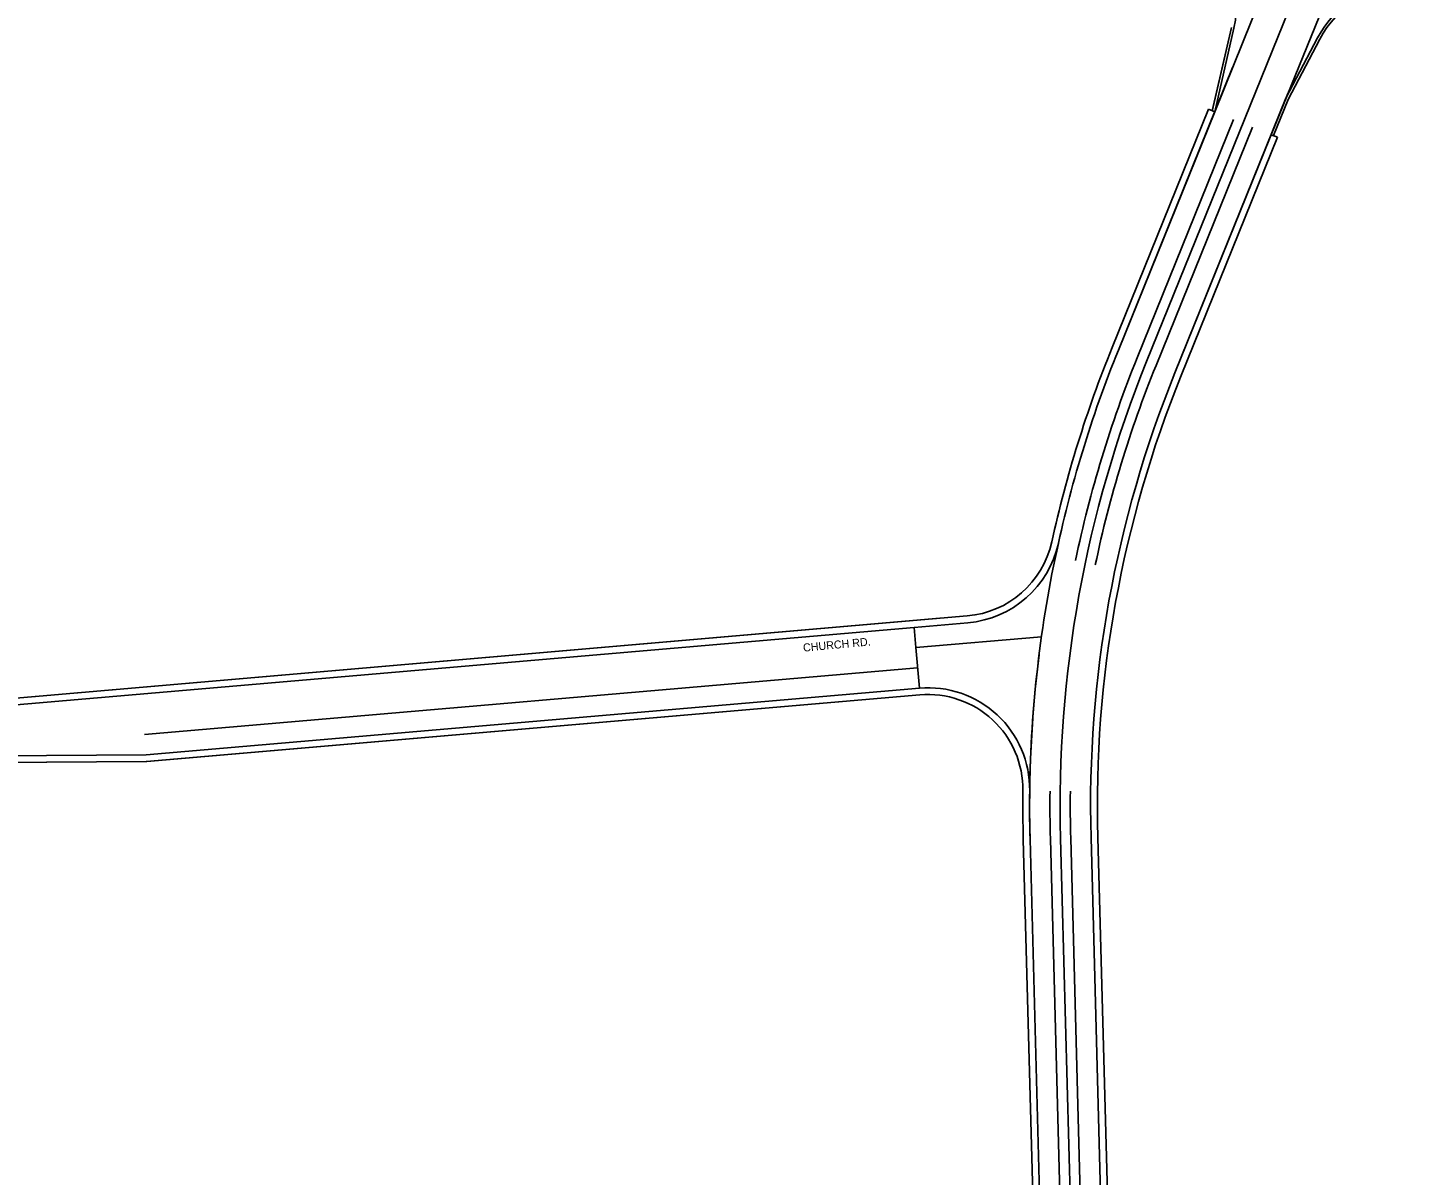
# Model space of a CAD drawing. Extents: x 2315515 to 2326910, y 758186 to 762794.
# Drawn here: x 2319969 to 2320783, y 758863 to 759540 of the extents above; entities that cross this region are included whole.
import ezdxf

# ---------------------------------------------------------------- set-up
doc = ezdxf.new("R2010")
doc.units = 0
for name, color, linetype in [('Default', 7, 'Continuous'), ('Draft_Corr_Range_Design', 7, 'Continuous'), ('E_Terrain_Exterior', 7, 'Continuous'), ('Pavement Marking Yellow', 7, 'Continuous'), ('Road_Curb_Face', 7, 'Continuous'), ('TL_End Condition Ditch In', 7, 'Continuous'), ('TL_End Condition Ditch Out', 7, 'Continuous'), ('TL_Pavement Centerline', 7, 'Continuous')]:
    doc.layers.add(name, color=color, linetype=linetype)

msp = doc.modelspace()

# ---------------------------------------------------------------- linework, layer by layer
at = {"layer": 'Default'}
for p, q in [((2320629.39, 759343.06), (2320782.39, 759721.29)), ((2320629.39, 759343.06), (2320782.39, 759721.29)), ((2320629.39, 759343.06), (2320782.39, 759721.29)), ((2320602.26, 758186.07), (2320578.57, 759061.64)), ((2320602.26, 758186.07), (2320578.57, 759061.64)), ((2320602.26, 758186.07), (2320578.57, 759061.64))]:
    msp.add_line(p, q, dxfattribs=at)
msp.add_arc((2321278.32, 759080.58), 700, 157.9768, 181.54992, dxfattribs=at)
msp.add_arc((2321278.32, 759080.58), 700, 157.9768, 181.54992, dxfattribs=at)
msp.add_arc((2321278.32, 759080.58), 700, 157.9768, 181.54992, dxfattribs=at)
at = {"layer": 'Draft_Corr_Range_Design'}
msp.add_line((2320037.8, 759122.94), (2320494.19, 759162.3), dxfattribs=at)
at = {"layer": 'E_Terrain_Exterior'}
for p, q in [((2320669.59, 759490.43), (2320680.92, 759539.79)), ((2320711.67, 759498.46), (2320730.38, 759534.04)), ((2320612.71, 759349.81), (2320680.17, 759516.61)), ((2320646.08, 759336.32), (2320712.75, 759501.15)), ((2320646.08, 759336.32), (2320711.67, 759498.46)), ((2320612.71, 759349.81), (2320669.59, 759490.43)), ((2319886.93, 759134.02), (2320492.13, 759186.22)), ((2320492.13, 759186.22), (2320523.86, 759188.95)), ((2320492.13, 759186.22), (2320523.86, 759188.95)), ((2320492.13, 759186.22), (2320493.16, 759174.26)), ((2320495.23, 759150.35), (2320493.16, 759174.26)), ((2320038.83, 759110.99), (2320495.23, 759150.35)), ((2320038.83, 759110.99), (2320495.23, 759150.35)), ((2319888.99, 759110.06), (2320038.83, 759110.99)), ((2320578.86, 758385.51), (2320560.58, 759061.16)), ((2320578.86, 758385.51), (2320560.58, 759061.16)), ((2320614.85, 758386.48), (2320596.57, 759062.13)), ((2320614.85, 758386.48), (2320596.57, 759062.13))]:
    msp.add_line(p, q, dxfattribs=at)
for centre, radius, start, end in [((2320632.19, 759550.98), 50, 347.06707, 72.9768), ((2320783.48, 759506.12), 60, 90.68739, 152.2662), ((2321278.32, 759080.58), 718, 157.9768, 168.14589), ((2321278.32, 759080.58), 718, 157.9768, 168.14589), ((2321278.32, 759080.58), 682, 157.9768, 181.54992), ((2321278.32, 759080.58), 682, 157.9768, 181.54992), ((2320518.71, 759248.73), 60, 274.92939, 347.5179), ((2320518.71, 759248.73), 60, 274.92939, 347.5179), ((2321278.32, 759080.58), 718, 172.83939, 181.54992), ((2320500.38, 759090.57), 60, 359.26403, 94.92939), ((2321278.32, 759080.58), 718, 179.26403, 181.54992)]:
    msp.add_arc(centre, radius, start, end, dxfattribs=at)
at = {"layer": 'Pavement Marking Yellow'}
for p, q in [((2320623.83, 759345.31), (2320680.71, 759485.93)), ((2320634.96, 759340.81), (2320691.84, 759481.43)), ((2320590.86, 758385.83), (2320572.58, 759061.48)), ((2320602.85, 758386.16), (2320584.57, 759061.81))]:
    msp.add_line(p, q, dxfattribs=at)
for radius, start, end in [(706, 157.9768, 168.14589), (694, 157.9768, 168.14589), (706, 179.26403, 181.54992), (694, 179.26403, 181.54992)]:
    msp.add_arc((2321278.32, 759080.58), radius, start, end, dxfattribs=at)
at = {"layer": 'Road_Curb_Face'}
for p, q in [((2320668.13, 759490.77), (2320679.46, 759540.12)), ((2320668.18, 759491), (2320679.46, 759540.12)), ((2320713, 759497.76), (2320731.7, 759533.35)), ((2320704.35, 759476.37), (2320713, 759497.76))]:
    msp.add_line(p, q, dxfattribs=at)
msp.add_arc((2320783.48, 759506.12), 58.5, 90.68739, 152.2662, dxfattribs=at)
at = {"layer": 'TL_End Condition Ditch In'}
for p, q in [((2320669.59, 759490.43), (2320729.28, 759638.01)), ((2320702.96, 759476.93), (2320758.72, 759614.78))]:
    msp.add_line(p, q, dxfattribs=at)
msp.add_arc((2321278.32, 759080.58), 718, 167.5179, 179.26403, dxfattribs=at)
at = {"layer": 'TL_End Condition Ditch Out'}
msp.add_line((2320493.16, 759174.26), (2320567.33, 759180.66), dxfattribs=at)
at = {"layer": 'TL_Pavement Centerline'}
for p, q in [((2320609, 759351.31), (2320665.88, 759491.93)), ((2320669.59, 759490.43), (2320665.88, 759491.93)), ((2320702.96, 759476.93), (2320706.67, 759475.43)), ((2320649.79, 759334.82), (2320706.67, 759475.43)), ((2319886.58, 759138), (2320523.52, 759192.94)), ((2319886.58, 759138), (2320507.36, 759191.54)), ((2320039.02, 759106.99), (2320495.57, 759146.36)), ((2320039.18, 759107), (2320495.57, 759146.36)), ((2319889.01, 759106.06), (2320038.86, 759106.99)), ((2319889.01, 759106.06), (2320039.02, 759106.99)), ((2320574.86, 758385.4), (2320556.58, 759061.05)), ((2320574.86, 758385.34), (2320556.58, 759061.05)), ((2320618.85, 758386.59), (2320600.57, 759062.24))]:
    msp.add_line(p, q, dxfattribs=at)
for centre, radius, start, end in [((2321278.32, 759080.58), 722, 157.9768, 167.5179), ((2321278.32, 759080.58), 678, 157.9768, 181.54992), ((2320518.71, 759248.73), 56, 274.92939, 347.5179), ((2320518.71, 759248.73), 56, 274.92939, 347.5179), ((2320500.38, 759090.57), 56, 359.26403, 94.92939), ((2321278.32, 759080.58), 722, 179.26403, 181.54992), ((2321278.32, 759080.58), 722, 179.26403, 181.54992)]:
    msp.add_arc(centre, radius, start, end, dxfattribs=at)

# ---------------------------------------------------------------- texts
at = {"layer": 'Default'}
msp.add_text('CHURCH RD.', height=4.724, rotation=5.35287, dxfattribs=at).set_placement((2320426.81, 759171.83))

doc.saveas('drawing.dxf')
